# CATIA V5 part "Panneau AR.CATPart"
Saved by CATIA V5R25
Part number: Panneau AR
Bounding box of the stored display mesh (mm): x -160 to 160, y -20 to 20, z 0 to 3
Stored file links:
  C:\Users\m000605\Desktop\Projet FAB liseuse\Panneau AR.CATPart
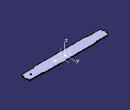
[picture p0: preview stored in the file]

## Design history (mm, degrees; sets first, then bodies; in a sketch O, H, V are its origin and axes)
AxisSystem1: origin (0, 0, 0), X (1, 0, 0), Y (0, 1, 0), Z (0, 0, 1)
Set1
  Sketch1 on XY plane of AxisSystem1, origin (0, 0, 0), H (1, 0, 0), V (0, 1, 0)
    line L1 (-160, 7) -> (-160, -7)
    line L2 (-160, -7) -> (-157, -7)
    line L3 (-107, -17) -> (-107, -20)
    line L4 (-107, -20) -> (107, -20)
    line L5 (107, -20) -> (107, -17)
    point P8 (157, -7)
    line L6 (157, -7) -> (160, -7)
    line L7 (160, -7) -> (160, 7)
    line L8 (160, 7) -> (157, 7)
    point P12 (107, 17)
    line L9 (107, 17) -> (107, 20)
    line L10 (-107, 20) -> (107, 20)
    line L11 (-107, 20) -> (-107, 17)
    line L12 (-157, 7) -> (-160, 7)
    reference intersected line E1 through (0, 0) direction (-1, 0) from ZX plane of AxisSystem1
    reference projected line E2 through (0, 0) direction (1, 0) from edge [XY plane of AxisSystem1 | ZX plane of AxisSystem1]
    line L13 (-107, -17) -> (-157, -17)
    line L14 (-157, -17) -> (-157, -7)
    line L15 (-157, 7) -> (-157, 17)
    line L16 (-157, 17) -> (-107, 17)
    line L17 (107, 17) -> (157, 17)
    line L18 (157, 17) -> (157, 7)
    line L19 (107, -17) -> (157, -17)
    point P20 (157, -17)
    line L20 (157, -17) -> (157, -7)
    reference intersected line E3 through (0, 0) direction (-1, 0) from ZX plane of AxisSystem1
    distance L4 L10 = 40
    distance L10 L17 = 3
    distance L13 L4 = 3
    distance L19 L6 = 10
    distance L7 L1 = 320
    distance L18 L9 = 50
    distance L20 L7 = 3
    distance L15 L11 = 50
    distance L1 L15 = 3
    distance L12 L16 = 10
    distance L14 L3 = 50
    vertical: L1 V, L3 V, L5 V, L7 V, L9 V, L11 V, L14 V, L15 V, L18 V, L20 V
    horizontal: L2 H, L4 H, L6 H, L8 H, L10 H, L12 H, L13 H, L16 H, L17 H, L19 H
    coincidence: P8 L2, P12 L5, P20 L18
    symmetry: L1 L7 V, L4 L10 E1, L8 L6 E2, L20 L14 V, L19 L17 H, L13 L16 E3
Body1 (main body)
  Pad1: profile Sketch1, direction (0, 0, 1), length 3
  Sketch2 on end face of Pad1, origin (0, 0, 3), H (1, 0, 0), V (0, 1, 0)
    circle A1 centre (135, 0) radius 2.75
    point P1 (135, 0)
    point P2 (132.25, 0)
    reference projected line E1 (160, -7) -> (160, 7) from edge [face of Pad1 from Sketch1.L7 | end face of Pad1]
    radius A1 = 2.75
    distance E1 P1 = 25
    coincidence: A1 P2, P2 H, P1 H
  Pocket1: profile Sketch2, direction (0, 0, -1), length 3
